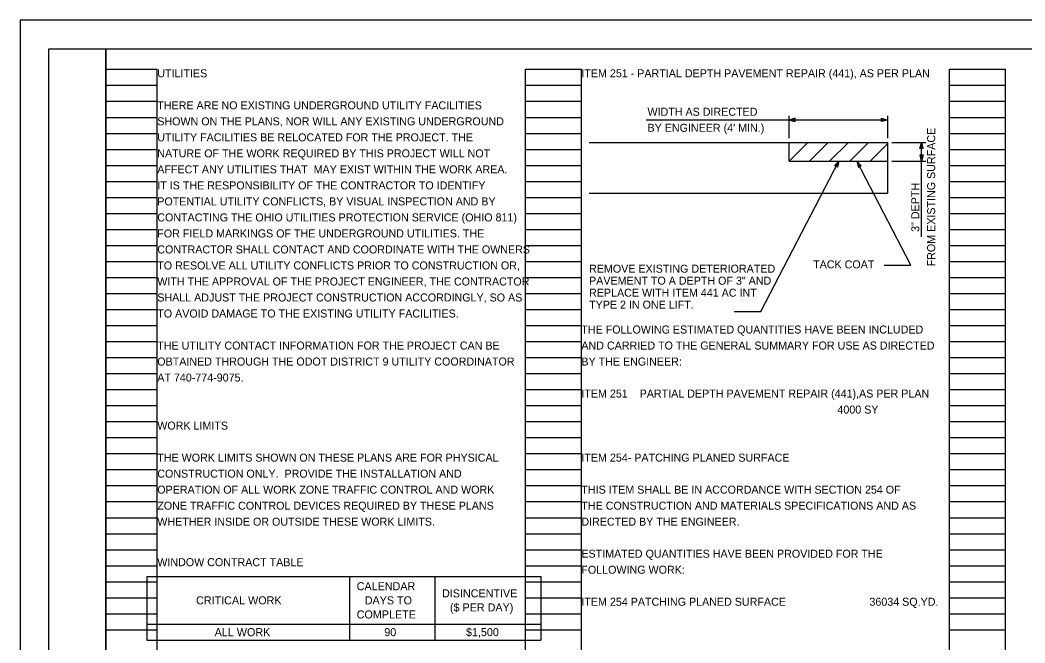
# Model space of a CAD drawing. Extents: x 0 to 34, y 0 to 22.
# Drawn here: x 0 to 17.58, y 11.11 to 22 of the extents above; entities that cross this region are included whole.
import ezdxf

# ---------------------------------------------------------------- set-up
doc = ezdxf.new("R2010")
doc.units = 0
for name, color, linetype in [('Default', 7, 'Continuous'), ('SH_Border', 7, 'Continuous'), ('SH_Cut_Line', 7, 'Continuous'), ('SH_Data', 7, 'Continuous'), ('SH_Text', 7, 'Continuous'), ('TX_P_1', 7, 'Continuous')]:
    doc.layers.add(name, color=color, linetype=linetype)

msp = doc.modelspace()

# ---------------------------------------------------------------- linework, layer by layer
at = {"layer": 'Default'}
for p, q in [((2.22, 12.272), (9.112, 12.272)), ((2.22, 12.272), (2.22, 11.159)), ((5.763, 12.272), (5.763, 11.159)), ((7.254, 12.272), (7.254, 11.159)), ((9.112, 12.272), (9.112, 11.159)), ((2.22, 11.437), (9.112, 11.437)), ((2.22, 11.159), (9.112, 11.159))]:
    msp.add_line(p, q, dxfattribs=at)
at = {"layer": 'SH_Border'}
for points in [[(0.5, 21.5), (1.5, 21.5), (1.5, 0.5), (0.5, 0.5)], [(1.5, 21.5), (33.5, 21.5), (33.5, 0.5), (1.5, 0.5)]]:
    msp.add_lwpolyline(points, close=True, dxfattribs=at)
at = {"layer": 'SH_Cut_Line'}
msp.add_lwpolyline([(0, 0), (34, 0), (34, 22), (0, 22)], close=True, dxfattribs=at)
at = {"layer": 'SH_Data'}
for p, q in [((1.5, 0.98), (1.5, 21.14)), ((1.5, 21.14), (2.4, 21.14)), ((2.4, 0.98), (2.4, 21.14)), ((8.84, 0.98), (8.84, 21.14)), ((8.84, 21.14), (9.82, 21.14)), ((9.82, 0.98), (9.82, 21.14)), ((16.26, 0.98), (16.26, 21.14)), ((16.26, 21.14), (17.24, 21.14)), ((17.24, 0.98), (17.24, 21.14)), ((1.5, 20.86), (2.4, 20.86)), ((8.84, 20.86), (9.82, 20.86)), ((16.26, 20.86), (17.24, 20.86)), ((1.5, 20.58), (2.4, 20.58)), ((8.84, 20.58), (9.82, 20.58)), ((16.26, 20.58), (17.24, 20.58)), ((1.5, 20.3), (2.4, 20.3)), ((8.84, 20.3), (9.82, 20.3)), ((16.26, 20.3), (17.24, 20.3)), ((1.5, 20.02), (2.4, 20.02)), ((8.84, 20.02), (9.82, 20.02)), ((16.26, 20.02), (17.24, 20.02)), ((1.5, 19.74), (2.4, 19.74)), ((8.84, 19.74), (9.82, 19.74)), ((16.26, 19.74), (17.24, 19.74)), ((1.5, 19.46), (2.4, 19.46)), ((8.84, 19.46), (9.82, 19.46)), ((16.26, 19.46), (17.24, 19.46)), ((1.5, 19.18), (2.4, 19.18)), ((8.84, 19.18), (9.82, 19.18)), ((16.26, 19.18), (17.24, 19.18)), ((1.5, 18.9), (2.4, 18.9)), ((8.84, 18.9), (9.82, 18.9)), ((16.26, 18.9), (17.24, 18.9)), ((1.5, 18.62), (2.4, 18.62)), ((8.84, 18.62), (9.82, 18.62)), ((16.26, 18.62), (17.24, 18.62)), ((1.5, 18.34), (2.4, 18.34)), ((8.84, 18.34), (9.82, 18.34)), ((16.26, 18.34), (17.24, 18.34)), ((1.5, 18.06), (2.4, 18.06)), ((8.84, 18.06), (9.82, 18.06)), ((16.26, 18.06), (17.24, 18.06)), ((1.5, 17.78), (2.4, 17.78)), ((8.84, 17.78), (9.82, 17.78)), ((16.26, 17.78), (17.24, 17.78)), ((1.5, 17.5), (2.4, 17.5)), ((8.84, 17.5), (9.82, 17.5)), ((16.26, 17.5), (17.24, 17.5)), ((1.5, 17.22), (2.4, 17.22)), ((8.84, 17.22), (9.82, 17.22)), ((16.26, 17.22), (17.24, 17.22)), ((1.5, 16.94), (2.4, 16.94)), ((8.84, 16.94), (9.82, 16.94)), ((16.26, 16.94), (17.24, 16.94)), ((1.5, 16.66), (2.4, 16.66)), ((8.84, 16.66), (9.82, 16.66)), ((16.26, 16.66), (17.24, 16.66)), ((1.5, 16.38), (2.4, 16.38)), ((8.84, 16.38), (9.82, 16.38)), ((16.26, 16.38), (17.24, 16.38)), ((1.5, 16.1), (2.4, 16.1)), ((8.84, 16.1), (9.82, 16.1)), ((16.26, 16.1), (17.24, 16.1)), ((1.5, 15.82), (2.4, 15.82)), ((8.84, 15.82), (9.82, 15.82)), ((16.26, 15.82), (17.24, 15.82)), ((1.5, 15.54), (2.4, 15.54)), ((8.84, 15.54), (9.82, 15.54)), ((16.26, 15.54), (17.24, 15.54)), ((1.5, 15.26), (2.4, 15.26)), ((8.84, 15.26), (9.82, 15.26)), ((16.26, 15.26), (17.24, 15.26)), ((1.5, 14.98), (2.4, 14.98)), ((8.84, 14.98), (9.82, 14.98)), ((16.26, 14.98), (17.24, 14.98)), ((1.5, 14.7), (2.4, 14.7)), ((8.84, 14.7), (9.82, 14.7)), ((16.26, 14.7), (17.24, 14.7)), ((1.5, 14.42), (2.4, 14.42)), ((8.84, 14.42), (9.82, 14.42)), ((16.26, 14.42), (17.24, 14.42)), ((1.5, 14.14), (2.4, 14.14)), ((8.84, 14.14), (9.82, 14.14)), ((16.26, 14.14), (17.24, 14.14)), ((1.5, 13.86), (2.4, 13.86)), ((8.84, 13.86), (9.82, 13.86)), ((16.26, 13.86), (17.24, 13.86)), ((1.5, 13.58), (2.4, 13.58)), ((8.84, 13.58), (9.82, 13.58)), ((16.26, 13.58), (17.24, 13.58)), ((1.5, 13.3), (2.4, 13.3)), ((8.84, 13.3), (9.82, 13.3)), ((16.26, 13.3), (17.24, 13.3)), ((1.5, 13.02), (2.4, 13.02)), ((8.84, 13.02), (9.82, 13.02)), ((16.26, 13.02), (17.24, 13.02)), ((1.5, 12.74), (2.4, 12.74)), ((8.84, 12.74), (9.82, 12.74)), ((16.26, 12.74), (17.24, 12.74)), ((1.5, 12.46), (2.4, 12.46)), ((8.84, 12.46), (9.82, 12.46)), ((16.26, 12.46), (17.24, 12.46)), ((1.5, 12.18), (2.4, 12.18)), ((8.84, 12.18), (9.82, 12.18)), ((16.26, 12.18), (17.24, 12.18)), ((1.5, 11.9), (2.4, 11.9)), ((8.84, 11.9), (9.82, 11.9)), ((16.26, 11.9), (17.24, 11.9)), ((1.5, 11.62), (2.4, 11.62)), ((8.84, 11.62), (9.82, 11.62)), ((16.26, 11.62), (17.24, 11.62)), ((1.5, 11.34), (2.4, 11.34)), ((8.84, 11.34), (9.82, 11.34)), ((16.26, 11.34), (17.24, 11.34))]:
    msp.add_line(p, q, dxfattribs=at)
at = {"layer": 'SH_Text'}
for p, q in [((15.179, 20.253), (10.956, 20.253)), ((13.457, 19.937), (13.457, 20.328)), ((15.179, 19.937), (15.179, 20.328)), ((9.955, 19.862), (15.179, 19.862)), ((13.457, 19.534), (13.457, 19.862)), ((13.457, 19.534), (13.785, 19.862)), ((13.811, 19.534), (14.139, 19.862)), ((14.164, 19.534), (14.492, 19.862)), ((14.518, 19.534), (14.846, 19.862)), ((14.871, 19.534), (15.179, 19.841)), ((15.179, 18.976), (15.179, 19.862)), ((15.254, 19.862), (15.844, 19.862)), ((15.769, 18.212), (15.769, 19.862)), ((12.961, 16.904), (14.325, 19.534)), ((13.457, 19.534), (15.179, 19.534)), ((15.586, 17.714), (14.642, 19.534)), ((15.254, 19.534), (15.844, 19.534)), ((9.955, 18.976), (15.179, 18.976)), ((15.119, 17.714), (15.586, 17.714)), ((12.493, 16.904), (12.961, 16.904))]:
    msp.add_line(p, q, dxfattribs=at)
for points in [[(13.457, 20.253), (13.563, 20.229), (13.563, 20.283)], [(15.179, 20.253), (15.073, 20.229), (15.073, 20.283)], [(15.769, 19.862), (15.793, 19.756), (15.74, 19.756)], [(14.325, 19.534), (14.301, 19.428), (14.253, 19.451)], [(14.642, 19.534), (14.666, 19.428), (14.715, 19.451)], [(15.771, 19.536), (15.747, 19.642), (15.8, 19.642)]]:
    msp.add_lwpolyline(points, close=True, dxfattribs=at)

# ---------------------------------------------------------------- texts
at = {"layer": 'Default'}
for s, height, p in [('CALENDAR ', 0.1408, (5.889, 12.031)), ('DISINCENTIVE ', 0.14076, (7.382, 11.907)), ('CRITICAL WORK', 0.14076, (3.079, 11.784)), ('DAYS TO ', 0.1408, (6.03, 11.784)), ('($ PER DAY)', 0.14076, (7.521, 11.661)), ('COMPLETE', 0.1408, (5.889, 11.538)), ('ALL WORK', 0.1408, (3.404, 11.228)), ('90', 0.1408, (6.372, 11.228)), ('$1,500', 0.1408, (7.801, 11.228))]:
    msp.add_text(s, height=height, dxfattribs=at).set_placement(p)
at = {"layer": 'SH_Text'}
for s, p in [('ITEM 251 - PARTIAL DEPTH PAVEMENT REPAIR (441), AS PER PLAN', (9.82, 21)), ('WIDTH AS DIRECTED', (10.977, 20.327)), ("BY ENGINEER (4' MIN.)", (10.977, 20.047)), ('TACK COAT', (13.875, 17.659)), ('REMOVE EXISTING DETERIORATED', (9.955, 17.584)), ('PAVEMENT TO A DEPTH OF 3" AND', (9.955, 17.374)), ('REPLACE WITH ITEM 441 AC INT', (9.955, 17.164)), ('TYPE 2 IN ONE LIFT.', (9.955, 16.954)), ('THE FOLLOWING ESTIMATED QUANTITIES HAVE BEEN INCLUDED', (9.82, 16.52)), ('AND CARRIED TO THE GENERAL SUMMARY FOR USE AS DIRECTED', (9.82, 16.24)), ('BY THE ENGINEER:', (9.82, 15.96)), ('ITEM 251    PARTIAL DEPTH PAVEMENT REPAIR (441),AS PER PLAN       ', (9.82, 15.4)), ('4000 SY', (14.3, 15.12)), ('WORK LIMITS', (2.4, 14.84)), ('THE WORK LIMITS SHOWN ON THESE PLANS ARE FOR PHYSICAL', (2.4, 14.28)), ('ITEM 254- PATCHING PLANED SURFACE', (9.82, 14.28)), ('CONSTRUCTION ONLY.  PROVIDE THE INSTALLATION AND', (2.4, 14)), ('OPERATION OF ALL WORK ZONE TRAFFIC CONTROL AND WORK', (2.4, 13.72)), ('THIS ITEM SHALL BE IN ACCORDANCE WITH SECTION 254 OF', (9.82, 13.72)), ('ZONE TRAFFIC CONTROL DEVICES REQUIRED BY THESE PLANS', (2.4, 13.44)), ('THE CONSTRUCTION AND MATERIALS SPECIFICATIONS AND AS', (9.82, 13.44)), ('WHETHER INSIDE OR OUTSIDE THESE WORK LIMITS.', (2.4, 13.16)), ('DIRECTED BY THE ENGINEER.', (9.82, 13.16)), ('ESTIMATED QUANTITIES HAVE BEEN PROVIDED FOR THE', (9.82, 12.6)), ('WINDOW CONTRACT TABLE', (2.4, 12.452)), ('FOLLOWING WORK:', (9.82, 12.32)), ('ITEM 254 PATCHING PLANED SURFACE', (9.82, 11.76)), ('36034 SQ.YD.', (14.86, 11.76))]:
    msp.add_text(s, height=0.14, dxfattribs=at).set_placement(p)
for s, p in [('FROM EXISTING SURFACE', (16.01, 17.694)), ('3" DEPTH', (15.732, 18.297))]:
    msp.add_text(s, height=0.14, rotation=90, dxfattribs=at).set_placement(p)
at = {"layer": 'TX_P_1'}
for s, p in [('UTILITIES', (2.4, 21)), ('THERE ARE NO EXISTING UNDERGROUND UTILITY FACILITIES ', (2.4, 20.44)), ('SHOWN ON THE PLANS, NOR WILL ANY EXISTING UNDERGROUND ', (2.4, 20.16)), ('UTILITY FACILITIES BE RELOCATED FOR THE PROJECT. THE', (2.4, 19.88)), ('NATURE OF THE WORK REQUIRED BY THIS PROJECT WILL NOT', (2.4, 19.6)), ('AFFECT ANY UTILITIES THAT  MAY EXIST WITHIN THE WORK AREA. ', (2.4, 19.32)), ('IT IS THE RESPONSIBILITY OF THE CONTRACTOR TO IDENTIFY ', (2.4, 19.04)), ('POTENTIAL UTILITY CONFLICTS, BY VISUAL INSPECTION AND BY ', (2.4, 18.76)), ('CONTACTING THE OHIO UTILITIES PROTECTION SERVICE (OHIO 811)', (2.4, 18.48)), ('FOR FIELD MARKINGS OF THE UNDERGROUND UTILITIES. THE ', (2.4, 18.2)), ('CONTRACTOR SHALL CONTACT AND COORDINATE WITH THE OWNERS ', (2.4, 17.92)), ('TO RESOLVE ALL UTILITY CONFLICTS PRIOR TO CONSTRUCTION OR, ', (2.4, 17.64)), ('WITH THE APPROVAL OF THE PROJECT ENGINEER, THE CONTRACTOR ', (2.4, 17.36)), ('SHALL ADJUST THE PROJECT CONSTRUCTION ACCORDINGLY, SO AS ', (2.4, 17.08)), ('TO AVOID DAMAGE TO THE EXISTING UTILITY FACILITIES.', (2.4, 16.8)), ('THE UTILITY CONTACT INFORMATION FOR THE PROJECT CAN BE ', (2.4, 16.24)), ('OBTAINED THROUGH THE ODOT DISTRICT 9 UTILITY COORDINATOR ', (2.4, 15.96)), ('AT 740-774-9075.', (2.4, 15.68))]:
    msp.add_text(s, height=0.14, dxfattribs=at).set_placement(p)

doc.saveas('drawing.dxf')
